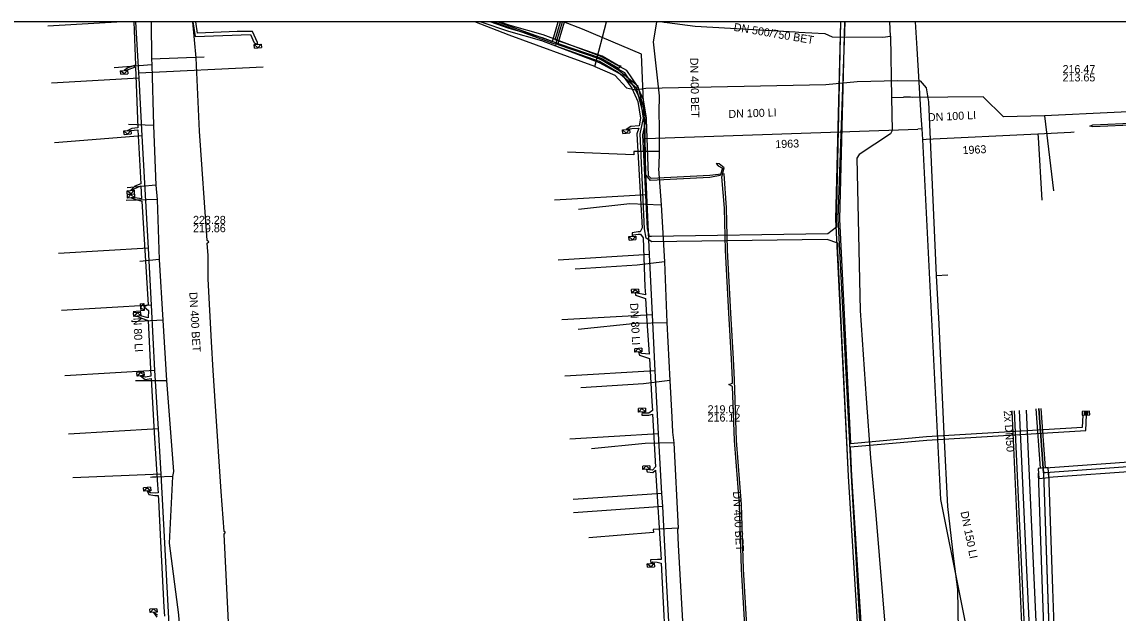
# Model space of a CAD drawing. Extents: x -599951 to -598963, y -1164095 to -1162939.
# Drawn here: x -599392.1 to -599282.6, y -1162998.5 to -1162939.4 of the extents above; entities that cross this region are included whole.
import ezdxf

# ---------------------------------------------------------------- set-up
doc = ezdxf.new("R2010")
doc.units = 0
for name, color, linetype in [('28', 7, 'Continuous'), ('31', 7, 'Continuous'), ('Vrstva 12', 7, 'Continuous'), ('Vrstva 13', 7, 'Continuous'), ('Vrstva 15', 7, 'Continuous'), ('Vrstva 19', 7, 'Continuous'), ('Vrstva 25', 7, 'Continuous'), ('Vrstva 26', 7, 'Continuous'), ('Vrstva 27', 7, 'Continuous'), ('Vrstva 28', 7, 'Continuous'), ('Vrstva 37', 7, 'Continuous'), ('Vrstva 38', 7, 'Continuous'), ('Vrstva 42', 7, 'Continuous'), ('Vrstva 43', 7, 'Continuous'), ('Vrstva 44', 7, 'Continuous'), ('Vrstva 53', 7, 'Continuous'), ('Vrstva 55', 7, 'Continuous')]:
    doc.layers.add(name, color=color, linetype=linetype)

# ---------------------------------------------------------------- blocks, each defined once
blk = doc.blocks.new('NN630')
at = {"layer": '31'}
for points in [[(-0.003, -0.7), (-0.703, 0)], [(-0.703, -0.7), (-0.703, 0), (0.697, 0), (0.697, -0.7)], [(-0.003, -0.7), (0.697, 0)], [(-0.703, -0.7), (0.697, -0.7)]]:
    blk.add_lwpolyline(points, dxfattribs=at)
blk = doc.blocks.new('NN620')
at = {"layer": '28'}
for points in [[(0.752, 0.004), (-0.748, 0.004)], [(-0.748, 0.004), (-0.748, -0.746)], [(0.752, -0.746), (0.752, 0.004)], [(-0.748, -0.746), (0.752, -0.746)], [(0.368, -0.18), (-0.376, -0.18)], [(-0.376, -0.18), (-0.376, -0.558)], [(-0.376, -0.558), (0.368, -0.558)], [(0.321, -0.227), (-0.329, -0.227)], [(-0.329, -0.227), (-0.329, -0.51)], [(-0.329, -0.51), (0.321, -0.51)], [(0.274, -0.274), (-0.281, -0.274)], [(-0.281, -0.274), (-0.281, -0.463)], [(-0.281, -0.463), (0.274, -0.463)], [(0.227, -0.321), (-0.234, -0.321)], [(-0.234, -0.321), (-0.234, -0.416)], [(-0.234, -0.416), (0.227, -0.416)], [(-0.193, -0.369), (0.185, -0.369)], [(0.227, -0.416), (0.227, -0.321)], [(0.274, -0.463), (0.274, -0.274)], [(0.321, -0.51), (0.321, -0.227)], [(0.368, -0.558), (0.368, -0.18)]]:
    blk.add_lwpolyline(points, dxfattribs=at)

msp = doc.modelspace()

# ---------------------------------------------------------------- linework, layer by layer
at = {"layer": 'Vrstva 13'}
for p, q in [((-599382.048, -1162939.4), (-599389.492, -1162939.822)), ((-599380.421, -1162944.491), (-599367.977, -1162943.893)), ((-599380.39, -1162945.01), (-599389.156, -1162945.507)), ((-599302.145, -1162950.094), (-599302.247, -1162948.793)), ((-599329.88, -1162951.055), (-599329.889, -1162949.86)), ((-599302.145, -1162950.094), (-599302.58, -1162950.11)), ((-599302.071, -1162951.135), (-599302.145, -1162950.094)), ((-599380.077, -1162950.799), (-599388.841, -1162951.471)), ((-599302.071, -1162951.135), (-599301.73, -1162951.11)), ((-599329.655, -1162956.664), (-599338.86, -1162957.22)), ((-599379.452, -1162962.026), (-599388.448, -1162962.56)), ((-599329.394, -1162962.653), (-599338.508, -1162963.208)), ((-599379.15, -1162967.72), (-599388.146, -1162968.254)), ((-599329.08, -1162968.678), (-599338.142, -1162969.182)), ((-599378.82, -1162974.23), (-599387.816, -1162974.764)), ((-599328.799, -1162974.276), (-599337.832, -1162974.8)), ((-599378.45, -1162980.06), (-599387.446, -1162980.594)), ((-599328.478, -1162980.575), (-599337.353, -1162981.085)), ((-599378.171, -1162984.588), (-599387.021, -1162984.975)), ((-599328.151, -1162986.54), (-599337.015, -1162987.129)), ((-599328.043, -1162987.835), (-599336.975, -1162988.469))]:
    msp.add_line(p, q, dxfattribs=at)
for points in [[(-599376.539, -1163014.958), (-599376.655, -1163012.839), (-599377.319, -1163000.888), (-599378.171, -1162984.588), (-599378.45, -1162980.06), (-599378.82, -1162974.23), (-599379.15, -1162967.72), (-599379.452, -1162962.026), (-599380.077, -1162950.799), (-599380.39, -1162945.01), (-599380.421, -1162944.491), (-599380.722, -1162939.4)], [(-599329.889, -1162949.86), (-599330.168, -1162942.626), (-599336.07, -1162940.12), (-599337.987, -1162939.4)], [(-599302.247, -1162948.793), (-599302.636, -1162942.043), (-599302.793, -1162939.4)], [(-599329.88, -1162951.055), (-599328.79, -1162951.02), (-599302.58, -1162950.11)], [(-599326.68, -1163013.53), (-599326.948, -1163008.293), (-599327.64, -1162995.76), (-599328.043, -1162987.835), (-599328.151, -1162986.54), (-599328.478, -1162980.575), (-599328.799, -1162974.276), (-599329.08, -1162968.678), (-599329.394, -1162962.653), (-599329.655, -1162956.664), (-599329.88, -1162951.055)], [(-599287.66, -1163147.47), (-599287.596, -1163147.153), (-599291.469, -1163082.154), (-599292.48, -1163063.001), (-599295.243, -1163012.163), (-599300.148, -1162987.801), (-599300.278, -1162987.115), (-599302.071, -1162951.135)], [(-599301.73, -1162951.11), (-599290.564, -1162950.572), (-599287.27, -1162950.41), (-599286.946, -1162950.391)], [(-599290.564, -1162950.572), (-599290.539, -1162950.942), (-599290.187, -1162957.226)]]:
    msp.add_lwpolyline(points, dxfattribs=at)
at = {"layer": 'Vrstva 19'}
msp.add_line((-599305.3, -1162940.83), (-599305.357, -1162939.4), dxfattribs=at)
for points in [[(-599379.168, -1162939.4), (-599379.16, -1162943.1), (-599379.12, -1162943.7), (-599378.94, -1162949.75), (-599378.72, -1162955.7), (-599378.58, -1162957.14), (-599378.39, -1162963.15), (-599378, -1162969.19), (-599377.66, -1162975.24), (-599376.95, -1162984.34), (-599377.05, -1162984.82), (-599377.38, -1162991.49), (-599376.45, -1162998.64), (-599375.963, -1163006.441), (-599375.51, -1163013.7), (-599375.25, -1163017.78), (-599374.71, -1163029.16), (-599374.34, -1163035.46), (-599374.33, -1163035.67), (-599374.09, -1163038.05), (-599374.03, -1163042.23), (-599373.154, -1163056.939)], [(-599328.686, -1162939.4), (-599328.861, -1162940.413), (-599329.03, -1162941.398)], [(-599328.093, -1162939.4), (-599327.906, -1162939.432), (-599327.603, -1162939.47), (-599324.81, -1162939.816), (-599314.818, -1162940.405), (-599314.453, -1162940.423), (-599311.873, -1162940.553), (-599311.133, -1162940.88), (-599306.076, -1162940.922), (-599305.3, -1162940.83), (-599305.18, -1162946.96), (-599304.004, -1162946.928)], [(-599329.03, -1162941.398), (-599328.43, -1162946.79), (-599328.44, -1162948.43), (-599328.43, -1162949.96), (-599328.42, -1162952.35), (-599328.46, -1162953.86), (-599328.47, -1162954.08), (-599328.21, -1162957.68), (-599327.88, -1162963.39), (-599327.66, -1162969.43), (-599327.34, -1162975.25), (-599327.15, -1162978.91), (-599327.08, -1162980.4), (-599326.96, -1162981.47), (-599326.52, -1162989.98), (-599326.59, -1162990.17), (-599326.51, -1162991.69), (-599325.41, -1163010.98), (-599325.37, -1163011.57), (-599325.34, -1163012.71), (-599325.32, -1163013.09), (-599324.53, -1163022.27), (-599324.49, -1163023.77)], [(-599379.16, -1162943.1), (-599373.879, -1162942.895)], [(-599379.12, -1162943.7), (-599382.874, -1162943.98)], [(-599259.67, -1162945.37), (-599259.6, -1162946.27), (-599259.57, -1162947.17), (-599270.46, -1162947.85), (-599275.985, -1162948.111), (-599289.905, -1162948.792), (-599293.991, -1162948.89), (-599296.04, -1162946.893), (-599303.085, -1162946.947), (-599303.29, -1162946.931), (-599304.004, -1162946.928)], [(-599305.18, -1162946.96), (-599305.12, -1162950.24), (-599305.28, -1162950.58), (-599308.44, -1162952.65), (-599308.65, -1162953), (-599308.33, -1162968.25), (-599307.74, -1162977.05), (-599307.31, -1162982.96), (-599306.76, -1162988.68), (-599305.75, -1163000.8), (-599300.22, -1163005.05), (-599294.44, -1163004.51), (-599294.34, -1163005.23)], [(-599289.905, -1162948.792), (-599289.016, -1162956.264)], [(-599378.94, -1162949.75), (-599381.46, -1162949.64)], [(-599328.42, -1162952.35), (-599330.96, -1162952.36), (-599330.96, -1162952.68), (-599337.57, -1162952.43)], [(-599378.72, -1162955.7), (-599381.571, -1162955.966)], [(-599378.58, -1162957.14), (-599381.678, -1162957.249)], [(-599336.49, -1162958.11), (-599331.34, -1162957.55)], [(-599331.34, -1162957.55), (-599328.21, -1162957.68)], [(-599378.39, -1162963.15), (-599380.33, -1162963.33)], [(-599330.61, -1162963.7), (-599336.82, -1162964.1)], [(-599327.88, -1162963.39), (-599330.61, -1162963.7)], [(-599381.081, -1162969.374), (-599381.09, -1162969.23)], [(-599378, -1162969.19), (-599381.081, -1162969.374)], [(-599336.52, -1162970.09), (-599330.75, -1162969.52)], [(-599330.75, -1162969.52), (-599327.66, -1162969.43)], [(-599380.76, -1162975.24), (-599377.66, -1162975.24)], [(-599327.34, -1162975.25), (-599329.99, -1162975.57)], [(-599329.99, -1162975.57), (-599336.25, -1162975.98)], [(-599329.81, -1162981.53), (-599335.19, -1162982.07)], [(-599326.96, -1162981.47), (-599329.81, -1162981.53)], [(-599377.05, -1162984.82), (-599378.693, -1162984.891), (-599379.052, -1162984.906), (-599379.26, -1162984.915)], [(-599326.52, -1162989.98), (-599329.01, -1162990.12), (-599328.98, -1162990.42), (-599335.43, -1162990.95)]]:
    msp.add_lwpolyline(points, dxfattribs=at)
at = {"layer": 'Vrstva 25'}
for p, q in [((-599334.842, -1162943.839), (-599333.67, -1162939.4)), ((-599290.017, -1162984.479), (-599290.485, -1162978.048))]:
    msp.add_line(p, q, dxfattribs=at)
for points in [[(-599334.842, -1162943.839), (-599343.416, -1162940.712), (-599346.822, -1162939.4)], [(-599334.842, -1162943.839), (-599332.847, -1162944.735), (-599331.692, -1162945.98), (-599330.791, -1162946.189), (-599329.747, -1162946.007), (-599311.771, -1162945.661), (-599308.632, -1162945.344), (-599304.556, -1162945.27), (-599302.339, -1162945.294), (-599301.746, -1162945.982), (-599301.498, -1162947.398), (-599300.733, -1162964.746)], [(-599300.733, -1162964.746), (-599299.57, -1162964.692)], [(-599300.733, -1162964.746), (-599300.469, -1162969.62), (-599299.949, -1162980.551), (-599299.608, -1162987.828), (-599299.004, -1162993.074), (-599298.585, -1162996.107), (-599298.467, -1163004.22), (-599298.411, -1163008.238), (-599298.555, -1163012.651)], [(-599272.917, -1162983.235), (-599289.802, -1162984.463), (-599290.017, -1162984.479)], [(-599290.017, -1162984.479), (-599289.606, -1162996.071), (-599289.16, -1163008.65), (-599316.731, -1163010.607), (-599316.004, -1163030.112), (-599315.215, -1163051.283)]]:
    msp.add_lwpolyline(points, dxfattribs=at)
at = {"layer": 'Vrstva 26'}
for p, q in [((-599290.302, -1162983.997), (-599290.734, -1162978.066)), ((-599289.804, -1162983.962), (-599290.236, -1162978.03)), ((-599289.804, -1162983.962), (-599273.417, -1162982.77)), ((-599272.417, -1162983.7), (-599289.5, -1162984.942))]:
    msp.add_line(p, q, dxfattribs=at)
for points in [[(-599315.733, -1163050.809), (-599316.504, -1163030.131), (-599317.248, -1163010.143), (-599289.677, -1163008.185), (-599290.106, -1162996.089), (-599290.517, -1162984.497)], [(-599289.517, -1162984.461), (-599289.106, -1162996.054), (-599288.643, -1163009.115), (-599316.213, -1163011.072), (-599315.504, -1163030.093), (-599314.716, -1163051.265)]]:
    msp.add_lwpolyline(points, dxfattribs=at)
at = {"layer": 'Vrstva 27'}
msp.add_lwpolyline([(-599290.479, -1162985.014), (-599289.482, -1162984.941), (-599289.555, -1162983.944), (-599290.552, -1162984.017)], close=True, dxfattribs=at)
at = {"layer": 'Vrstva 37'}
for points in [[(-599290.485, -1162978.048), (-599290.017, -1162984.479), (-599289.156, -1163008.706), (-599316.634, -1163010.66), (-599315.123, -1163051.266), (-599334.6, -1163052.28), (-599334.32, -1163059.62), (-599376.96, -1163062.17), (-599376.46, -1163077.4), (-599383.092, -1163077.483)], [(-599292.436, -1162978.249), (-599291.143, -1163006.497), (-599291.245, -1163006.778), (-599317.317, -1163008.775), (-599318.78, -1163008.949), (-599316.627, -1163069.826), (-599308.259, -1163069.607)], [(-599292.935, -1162978.272), (-599291.652, -1163006.308), (-599317.451, -1163008.283), (-599318.097, -1163008.6), (-599316.707, -1163069.9), (-599308.159, -1163069.65)]]:
    msp.add_lwpolyline(points, dxfattribs=at)
at = {"layer": 'Vrstva 38'}
for points in [[(-599308.24, -1163070.306), (-599317.302, -1163070.544), (-599319.502, -1163008.33), (-599317.385, -1163008.078), (-599291.861, -1163006.123), (-599293.135, -1162978.281)], [(-599291.737, -1162978.217), (-599290.437, -1163006.604), (-599290.741, -1163007.442), (-599317.249, -1163009.471), (-599318.058, -1163009.568), (-599315.952, -1163069.108), (-599308.277, -1163068.907)]]:
    msp.add_lwpolyline(points, dxfattribs=at)
at = {"layer": 'Vrstva 42'}
msp.add_line((-599310.687, -1162959.466), (-599310.252, -1162939.4), dxfattribs=at)
for points in [[(-599380.907, -1162939.4), (-599380.756, -1162943.709), (-599381.527, -1162943.999), (-599381.889, -1162944.248), (-599381.634, -1162944.228), (-599380.755, -1162943.888), (-599380.506, -1162949.979), (-599381.098, -1162950.06), (-599381.569, -1162950.273), (-599381.249, -1162950.256), (-599380.502, -1162950.172), (-599380.21, -1162955.571), (-599380.809, -1162955.815), (-599381.239, -1162956.239), (-599380.202, -1162955.792), (-599380.141, -1162957.075), (-599380.79, -1162956.986), (-599381.19, -1162956.989), (-599380.804, -1162957.121), (-599380.125, -1162957.324), (-599379.48, -1162967.658), (-599379.896, -1162967.886), (-599379.454, -1162968.245), (-599379.488, -1162968.968), (-599380.238, -1162968.775), (-599380.574, -1162968.803), (-599380.161, -1162969.015), (-599379.481, -1162969.227), (-599379.214, -1162974.788), (-599379.756, -1162974.912), (-599380.233, -1162974.765), (-599379.794, -1162975.121), (-599379.196, -1162975.022), (-599378.874, -1162980.45), (-599378.549, -1162985.677), (-599378.497, -1162986.473), (-599378.776, -1162986.493), (-599379.252, -1162986.466), (-599379.582, -1162986.277), (-599379.401, -1162986.645), (-599378.809, -1162986.713)], [(-599375.015, -1162939.4), (-599374.794, -1162940.846), (-599369.249, -1162940.65), (-599368.874, -1162941.486), (-599368.536, -1162941.644), (-599368.553, -1162941.461), (-599369.056, -1162940.348), (-599370.594, -1162940.363), (-599374.538, -1162940.535), (-599374.711, -1162939.4)], [(-599346.247, -1162939.4), (-599343.485, -1162940.328), (-599340.182, -1162941.268), (-599334.4, -1162943.444), (-599332.065, -1162944.712), (-599331.162, -1162946.022), (-599330.551, -1162947.346), (-599330.284, -1162949.002), (-599330.41, -1162949.795), (-599331.24, -1162949.843), (-599331.714, -1162950.167), (-599331.144, -1162950.048), (-599330.449, -1162950.008), (-599330.644, -1162950.588), (-599330.125, -1162959.986), (-599330.312, -1162960.392), (-599330.526, -1162960.387), (-599331.103, -1162960.472), (-599331.102, -1162960.829), (-599330.988, -1162960.676), (-599330.496, -1162960.605), (-599330.272, -1162960.627), (-599330.004, -1162960.994), (-599329.836, -1162965.866)], [(-599310.569, -1162962.287), (-599310.568, -1162961.512), (-599311.614, -1162961.144), (-599329.154, -1162961.383), (-599329.703, -1162960.996), (-599329.882, -1162960.078), (-599330.327, -1162950.59), (-599329.98, -1162949.004), (-599330.261, -1162947.258), (-599330.9, -1162945.873), (-599331.859, -1162944.483), (-599334.275, -1162943.171), (-599340.088, -1162940.983), (-599343.396, -1162940.041), (-599345.304, -1162939.4)], [(-599310.687, -1162959.466), (-599310.706, -1162959.923), (-599311.572, -1162960.591), (-599329.18, -1162960.839), (-599329.387, -1162960.851), (-599329.592, -1162960.087), (-599330.058, -1162950.68), (-599329.676, -1162949.006), (-599329.971, -1162947.17), (-599330.638, -1162945.724), (-599331.653, -1162944.254), (-599334.15, -1162942.898), (-599339.994, -1162940.698), (-599343.307, -1162939.754), (-599344.361, -1162939.4)], [(-599309.906, -1162939.4), (-599310.405, -1162959.12), (-599309.309, -1162981.528), (-599301.705, -1162980.834), (-599286.096, -1162979.889), (-599286.046, -1162978.74)], [(-599326.633, -1163029.066), (-599325.551, -1163029.042), (-599325.699, -1163031.314), (-599325.457, -1163048.064), (-599325.288, -1163054.96), (-599318.265, -1163054.466), (-599318.078, -1163053.65), (-599318.348, -1163048.216), (-599318.451, -1163046.377), (-599320.112, -1163013.118), (-599319.388, -1163009.694), (-599318.216, -1163007.447), (-599316.433, -1163005.686), (-599308.957, -1163001.374), (-599308.544, -1162999.916), (-599309.499, -1162984.786), (-599310.569, -1162962.287)], [(-599329.836, -1162965.866), (-599329.789, -1162966.68), (-599330.811, -1162966.48), (-599330.767, -1162966.722), (-599329.794, -1162967.049), (-599329.661, -1162969.305), (-599329.419, -1162972.614), (-599330.159, -1162972.539), (-599330.494, -1162972.386), (-599330.391, -1162972.7), (-599329.394, -1162973.033), (-599329.147, -1162977.337), (-599329.092, -1162978.225), (-599329.451, -1162978.51), (-599329.997, -1162978.484), (-599330.126, -1162978.375), (-599330.133, -1162978.686), (-599329.435, -1162978.714), (-599329.07, -1162978.593), (-599328.765, -1162983.87), (-599329.084, -1162984.2), (-599329.693, -1162984.116), (-599329.598, -1162984.371), (-599329.063, -1162984.436), (-599328.771, -1162984.213), (-599328.228, -1162993.111), (-599328.593, -1162993.136), (-599329.267, -1162993.161), (-599329.246, -1162993.526), (-599329.058, -1162993.374), (-599328.62, -1162993.379), (-599328.207, -1162993.479), (-599327.641, -1163004.615)], [(-599290.485, -1162978.048), (-599290.017, -1162984.479), (-599289.156, -1163008.706), (-599316.634, -1163010.66), (-599315.123, -1163051.266), (-599334.6, -1163052.28), (-599334.32, -1163059.62), (-599376.96, -1163062.17), (-599376.46, -1163077.4), (-599383.092, -1163077.483)], [(-599302.078, -1163013.294), (-599302.148, -1163012.777), (-599313.241, -1163013.297), (-599319.783, -1163013.256), (-599319.055, -1163009.813), (-599317.931, -1163007.657), (-599316.219, -1163005.967), (-599308.659, -1163001.606), (-599308.191, -1162999.954), (-599309.15, -1162984.766), (-599309.291, -1162981.878), (-599301.679, -1162981.183), (-599285.76, -1162980.219), (-599285.692, -1162978.677)], [(-599292.935, -1162978.272), (-599291.652, -1163006.308), (-599317.451, -1163008.283), (-599318.097, -1163008.6), (-599316.707, -1163069.9), (-599308.159, -1163069.65)], [(-599378.809, -1162986.713), (-599378.483, -1162986.717), (-599378.445, -1162987.154), (-599378.233, -1162991.324), (-599377.924, -1162997.902), (-599377.856, -1162998.804)], [(-599378.533, -1162998.701), (-599378.935, -1162998.416), (-599378.628, -1162998.877)]]:
    msp.add_lwpolyline(points, dxfattribs=at)
at = {"layer": 'Vrstva 44'}
for points in [[(-599308.544, -1162999.916), (-599309.499, -1162984.786), (-599310.755, -1162959.124), (-599310.256, -1162939.4)], [(-599309.872, -1162939.4), (-599310.548, -1162959.06), (-599309.232, -1162984.758), (-599308.369, -1162999.891)]]:
    msp.add_lwpolyline(points, dxfattribs=at)
at = {"layer": 'Vrstva 53'}
msp.add_lwpolyline([(-599951.125, -1164094.695), (-598963.215, -1164094.695), (-598963.215, -1162939.4), (-599951.125, -1162939.4)], close=True, dxfattribs=at)
at = {"layer": 'Vrstva 55'}
for points in [[(-599371.19, -1163004.83), (-599371.877, -1162990.601), (-599371.74, -1162990.39), (-599371.89, -1162990.33), (-599372.17, -1162986.33), (-599372.75, -1162977.81), (-599373, -1162974.22), (-599373.15, -1162971.37), (-599373.47, -1162965.08), (-599373.49, -1162962.75), (-599373.571, -1162961.514), (-599373.41, -1162961.37), (-599373.588, -1162961.25), (-599374.35, -1162950.31), (-599374.69, -1162942.99), (-599375.002, -1162939.4)], [(-599344.949, -1162939.4), (-599338.939, -1162941.558), (-599338.298, -1162941.609), (-599334.2, -1162943.01), (-599332.489, -1162944.013), (-599332.22, -1162943.82), (-599332.505, -1162943.771), (-599334.117, -1162942.824), (-599338.814, -1162941.18), (-599338.287, -1162939.4)], [(-599344.551, -1162939.4), (-599339.073, -1162941.341), (-599338.497, -1162939.4)], [(-599319.86, -1162999.737), (-599320.17, -1162994.104), (-599320.37, -1162987.626), (-599320.89, -1162981.246), (-599321.077, -1162975.838), (-599321.44, -1162975.63), (-599321.088, -1162975.503), (-599321.1, -1162975.164), (-599321.2, -1162973.075), (-599321.45, -1162968.506), (-599321.8, -1162962.224), (-599321.9, -1162958.005), (-599322.159, -1162954.882), (-599321.92, -1162953.97), (-599322.418, -1162953.594), (-599322.71, -1162953.56), (-599322.512, -1162953.787), (-599322.1, -1162954), (-599322.333, -1162954.759), (-599323.339, -1162954.94), (-599329.291, -1162955.252), (-599329.75, -1162954.68), (-599329.86, -1162949.12), (-599330.69, -1162946.01), (-599332.509, -1162944.442), (-599334.376, -1162943.342), (-599338.733, -1162941.825), (-599338.664, -1162941.378), (-599338.078, -1162939.4)], [(-599319.66, -1162999.723), (-599319.97, -1162994.096), (-599320.17, -1162987.614), (-599320.69, -1162981.234), (-599320.9, -1162975.156), (-599321, -1162973.065), (-599321.25, -1162968.494), (-599321.6, -1162962.216), (-599321.7, -1162957.995), (-599321.921, -1162954.587), (-599323.361, -1162954.74), (-599329.209, -1162955.048), (-599329.48, -1162954.77), (-599329.67, -1162949.11), (-599330.52, -1162945.87), (-599332.43, -1162944.24), (-599334.32, -1162943.12), (-599338.507, -1162941.692), (-599338.472, -1162941.435), (-599337.87, -1162939.4)], [(-599280.581, -1162949.675), (-599285.079, -1162949.898), (-599285.375, -1162949.812), (-599285.089, -1162949.698), (-599280.583, -1162949.475)]]:
    msp.add_lwpolyline(points, dxfattribs=at)

# ---------------------------------------------------------------- block references
at = {"layer": 'Vrstva 43'}
for name, p, xscale, yscale, rotation in [('NN630', (-599368.536, -1162941.644), 0.5, 0.5000000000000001, 4.000000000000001), ('NN630', (-599381.888, -1162944.248), 0.5, 0.5000000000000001, 4.000000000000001), ('NN630', (-599331.714, -1162950.167), 0.5000000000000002, 0.4999999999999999, 3.0000000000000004), ('NN630', (-599381.568, -1162950.273), 0.5, 0.5000000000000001, 4.000000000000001), ('NN630', (-599381.239, -1162956.24), 0.5, 0.5000000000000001, 4.000000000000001), ('NN630', (-599381.19, -1162956.989), 0.5, 0.5000000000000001, -176.00000000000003), ('NN630', (-599331.102, -1162960.829), 0.5, 0.5000000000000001, 4.000000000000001), ('NN630', (-599330.811, -1162966.48), 0.5, 0.5000000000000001, -176.00000000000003), ('NN630', (-599379.896, -1162967.886), 0.5, 0.5000000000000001, -86), ('NN630', (-599380.574, -1162968.804), 0.5, 0.5000000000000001, -176.00000000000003), ('NN630', (-599330.494, -1162972.386), 0.5000000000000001, 0.5, -177.00000000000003), ('NN630', (-599380.233, -1162974.765), 0.5, 0.5000000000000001, -176.00000000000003), ('NN630', (-599330.126, -1162978.375), 0.5000000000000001, 0.5, -177.00000000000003), ('NN620', (-599285.757, -1162978.687), 0.5000000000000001, 0.5, -177.00000000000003), ('NN630', (-599329.693, -1162984.116), 0.5000000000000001, 0.5, -177.00000000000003), ('NN630', (-599379.582, -1162986.277), 0.5, 0.5000000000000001, -176.00000000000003), ('NN630', (-599329.246, -1162993.526), 0.5, 0.5000000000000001, 4.000000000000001), ('NN630', (-599378.936, -1162998.416), 0.5000000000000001, 0.5, -177.00000000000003)]:
    msp.add_blockref(name, p, dxfattribs=dict(at, xscale=xscale, yscale=yscale, rotation=rotation))

# ---------------------------------------------------------------- texts
at = {"layer": 'Vrstva 12'}
for s, rotation, p in [('DN 500/750 BET', 350.47828, (-599321.005, -1162940.284)), ('DN 400 BET', 271.18093, (-599325.319, -1162942.984)), ('DN 400 BET', 273.35816, (-599375.373, -1162966.423)), ('DN 400 BET', 273.04371, (-599321.043, -1162986.335))]:
    msp.add_text(s, height=0.8, rotation=rotation, dxfattribs=at).set_placement(p)
for s, p in [('216.47', (-599288.099, -1162944.514)), ('213.65', (-599288.099, -1162945.346)), ('223.28', (-599375.001, -1162959.583)), ('219.86', (-599375.001, -1162960.415)), ('219.07', (-599323.574, -1162978.51)), ('216.12', (-599323.574, -1162979.342))]:
    msp.add_text(s, height=0.8, dxfattribs=at).set_placement(p)
at = {"layer": 'Vrstva 15'}
for s, rotation, p in [('DN 100 LI', 2.00535, (-599321.478, -1162949)), ('DN 100 LI', 2.7502, (-599301.539, -1162949.331)), ('1963', 2.00535, (-599316.797, -1162952.022)), ('1963', 2.7502, (-599298.077, -1162952.621)), ('DN 80 LI', 272.8998, (-599331.32, -1162967.514)), ('DN 80 LI', 273.01439, (-599381.018, -1162968.203)), ('DN 150 LI', 281.37957, (-599298.303, -1162988.38))]:
    msp.add_text(s, height=0.8, rotation=rotation, dxfattribs=at).set_placement(p)
at = {"layer": 'Vrstva 28'}
msp.add_text('2x DN50', height=0.8, rotation=274.16031, dxfattribs=at).set_placement((-599293.983, -1162978.257))

doc.saveas('drawing.dxf')
